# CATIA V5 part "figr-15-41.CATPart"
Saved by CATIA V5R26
Part number: Part1
Bounding box of the stored display mesh (mm): x -55.204 to 69.266, y -33.79 to 44.107, z 0 to 118.408
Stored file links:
  D:\_Deepak\CATIA\CATIA V5-6R2016_Deepak\Resources\Part files\Partfiles\c15_catia_v5_6r2016_prt\figr-15-41.CATPart
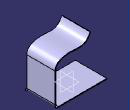
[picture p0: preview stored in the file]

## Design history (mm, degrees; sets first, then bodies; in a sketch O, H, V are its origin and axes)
SheetMetalParameters1: Thickness 2, BendRadius 4, KFactor 0.400515 {= log(min(100,max(20*SheetMetalParameters1.BendRadius,SheetMetalParameters1.Thickness)/SheetMetalParameters1.Thickness))/log(100)/2}, ReliefRadialLength 1, ReliefAxialLength 2, MinimumBendRadius 0
Body1 (main body)
  Sketch1 on xy-plane, origin (0, 0, 0), H (1, 0, 0), V (0, 1, 0)
    line L1 (-55.2037, 44.1067) -> (69.266, 44.1067)
    line L2 (69.266, 44.1067) -> (69.266, -33.7896)
    line L3 (69.266, -33.7896) -> (-55.2037, -33.7896)
    line L4 (-55.2037, -33.7896) -> (-55.2037, 44.1067)
    horizontal: L1 H, L3 H
    vertical: L2 V, L4 V
  Wall1: Thickness 2, Profile Sketch1, OffsetValue 0
  d_NewWallOnEdge1: NewWallOnEdge_Length 77.8964, NewWallOnEdge_HeightLimitOffset 0, NewWallOnEdge_WidthOffset1 -4, NewWallOnEdge_WidthOffset2 -4, NewWallOnEdge_Angle 90, NewWallOnEdge_BendRadiusValue 4 {= SheetMetalParameters1.BendRadius}, NewWallOnEdge_BendTable SheetMetalParameters1, NewWallOnEdge_GapValue 0, NewWallOnEdge_Edge edge [face of Wall1 | face of Wall1], KFacteur 0.400515 {= log(min(100,max(20*d_NewWallOnEdge1.Radius,SheetMetalParameters1.Thickness)/SheetMetalParameters1.Thickness))/log(100)/2}
  Sketch2 on face of d_NewWallOnEdge1, origin (0, 40.1067, 0), H (-1, 0, 0), V (0, 0, 1)
    spline S1 through (-69.266, 77.8964) (-67.9767, 84.9607) (-48.7678, 98.5965) (6.1586, 103.3856) (17.3621, 118.4076)
    reference projected line E1 (-69.266, 6) -> (-69.266, 77.8964) from edge [face of d_NewWallOnEdge1 | face of d_NewWallOnEdge1]
    reference projected line E2 (-69.266, 6) -> (-69.266, 77.8964) from edge [face of d_NewWallOnEdge1 | face of d_NewWallOnEdge1]
    reference projected point E3 (-69.266, 77.8964) from vertex [face of d_NewWallOnEdge1 | face of d_NewWallOnEdge1 | face of d_NewWallOnEdge1]
    point P1 (-69.266, 77.8964)
    coincidence: P1 E1, P1 E3
    tangency: S1 E2
  Flange1: Guide edge [face of d_NewWallOnEdge1 | face of d_NewWallOnEdge1], KFacteur 0.400515 {= SheetMetalParameters1.KFactor}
